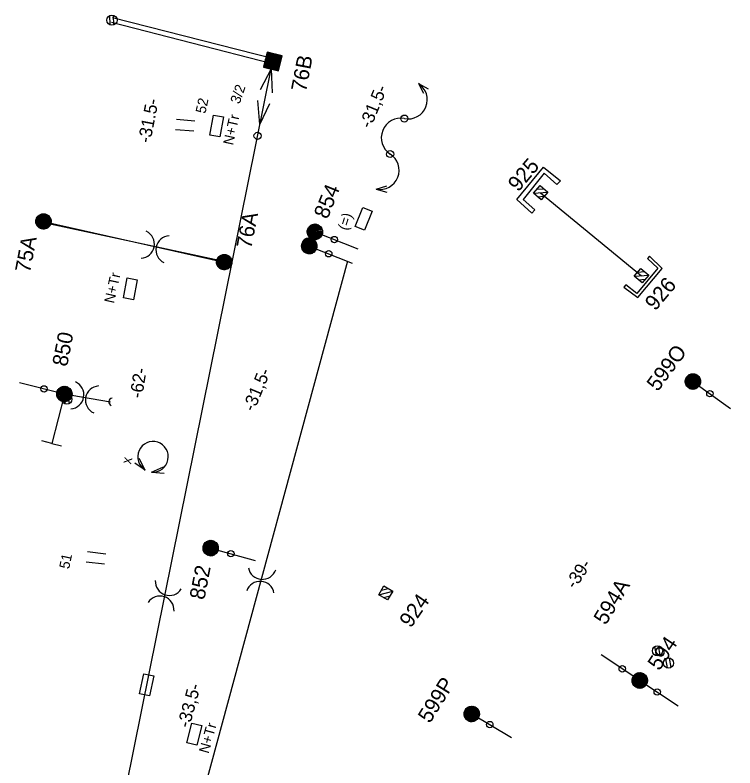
# Model space of a CAD drawing. Extents: x -595867 to -593796, y -1159595 to -1157495.
# Drawn here: x -594689.4 to -594618.9, y -1157851.2 to -1157777.4 of the extents above; entities that cross this region are included whole.
import ezdxf

# ---------------------------------------------------------------- set-up
doc = ezdxf.new("R2010")
doc.units = 0
for name, color, linetype in [('BVK_kanalizace_destova_nova', 7, 'Continuous'), ('BVK_kanalizace_jednotna_nova', 7, 'Continuous'), ('CD Telematika_novy', 7, 'Continuous'), ('Teplarny Horkovod', 7, 'Continuous')]:
    doc.layers.add(name, color=color, linetype=linetype)

# ---------------------------------------------------------------- blocks, each defined once
blk = doc.blocks.new('st_tecka')
blk.add_circle((0, 0), 0.00314)
blk = doc.blocks.new('st_1t')
for points in [[(-0.00711, 0.00221), (0.00057, 0.00744), (0.00185, 0.00722), (-0.00729, 0.00159)], [(-0.00689, 0.00294), (-0.00011, 0.00749), (0.00057, 0.00744), (-0.00711, 0.00221)], [(-0.00669, 0.00331), (-0.00149, 0.00733), (-0.00011, 0.00749), (-0.00689, 0.00294)], [(-0.00742, 0.00071), (0.00284, 0.0069), (0.00359, 0.00656), (-0.00747, -0.00023)], [(-0.00747, -0.00023), (0.00359, 0.00656), (0.00442, 0.00605), (-0.00743, -0.00101)], [(-0.00743, -0.00101), (0.00442, 0.00605), (0.00522, 0.0054), (-0.00722, -0.0019)], [(-0.00729, 0.00159), (0.00185, 0.00722), (0.00284, 0.0069), (-0.00742, 0.00071)], [(-0.00722, -0.0019), (0.00522, 0.0054), (0.00588, 0.00461), (-0.00688, -0.00302)], [(-0.00688, -0.00302), (0.00588, 0.00461), (0.00666, 0.00341), (-0.00639, -0.00386)], [(-0.00627, 0.00403), (-0.00222, 0.00714), (-0.00149, 0.00733), (-0.00669, 0.00331)], [(-0.00639, -0.00386), (0.00666, 0.00341), (0.00712, 0.00224), (-0.00567, -0.00488)], [(-0.00579, 0.00472), (-0.00315, 0.00675), (-0.00222, 0.00714), (-0.00627, 0.00403)], [(-0.00526, 0.00533), (-0.00413, 0.00624), (-0.00315, 0.00675), (-0.00579, 0.00472)], [(-0.00567, -0.00488), (0.00712, 0.00224), (0.00742, 0.00112), (-0.00488, -0.00564)], [(-0.00488, -0.00564), (0.00742, 0.00112), (0.00748, -0.00042), (-0.00405, -0.00629)], [(-0.00405, -0.00629), (0.00748, -0.00042), (0.00729, -0.00175), (-0.00317, -0.00679)], [(-0.00317, -0.00679), (0.00729, -0.00175), (0.00698, -0.00275), (-0.00206, -0.00718)], [(-0.00206, -0.00718), (0.00698, -0.00275), (0.00651, -0.0037), (-0.00114, -0.0074)], [(-0.00114, -0.0074), (0.00651, -0.0037), (0.00592, -0.00458), (-0.00048, -0.00747)], [(-0.00048, -0.00747), (0.00592, -0.00458), (0.00536, -0.00524), (0.00037, -0.00747)], [(0.00037, -0.00747), (0.00536, -0.00524), (0.00449, -0.00597), (0.00138, -0.00739)], [(0.00138, -0.00739), (0.00449, -0.00597), (0.00384, -0.00644), (0.0025, -0.00702)], [(0.0025, -0.00702), (0.00384, -0.00644), (0.00295, -0.00692), (0.00293, -0.00693)]]:
    blk.add_lwpolyline(points, close=True)
blk.add_circle((0, 0), 0.0075)
blk = doc.blocks.new('st1k_1t')
blk.add_line((0, 0), (0.04531, 0))
blk.add_blockref('st_1t', (0, 0))
at = {"rotation": 90}
blk.add_blockref('st_tecka', (0.02054, 0), dxfattribs=at)
blk = doc.blocks.new('st_2t')
for points in [[(-0.00748, 0.00968), (0.0002, 0.01491), (0.00148, 0.01469), (-0.00767, 0.00906)], [(-0.00727, 0.01041), (-0.00049, 0.01496), (0.0002, 0.01491), (-0.00748, 0.00968)], [(-0.00707, 0.01078), (-0.00187, 0.0148), (-0.00049, 0.01496), (-0.00727, 0.01041)], [(-0.00664, 0.0115), (-0.0026, 0.01461), (-0.00187, 0.0148), (-0.00707, 0.01078)], [(-0.00779, 0.00818), (0.00247, 0.01437), (0.00322, 0.01403), (-0.00784, 0.00724)], [(-0.00784, 0.00724), (0.00322, 0.01403), (0.00405, 0.01352), (-0.0078, 0.00646)], [(-0.0078, 0.00646), (0.00405, 0.01352), (0.00485, 0.01287), (-0.00759, 0.00557)], [(-0.00767, 0.00906), (0.00148, 0.01469), (0.00247, 0.01437), (-0.00779, 0.00818)], [(-0.00759, 0.00557), (0.00485, 0.01287), (0.0055, 0.01208), (-0.00725, 0.00445)], [(-0.00725, 0.00445), (0.0055, 0.01208), (0.00628, 0.01088), (-0.00676, 0.00361)], [(-0.00676, 0.00361), (0.00628, 0.01088), (0.00675, 0.00971), (-0.00604, 0.00259)], [(-0.00616, 0.01219), (-0.00352, 0.01422), (-0.0026, 0.01461), (-0.00664, 0.0115)], [(-0.00563, 0.0128), (-0.0045, 0.01371), (-0.00352, 0.01422), (-0.00616, 0.01219)], [(-0.00604, 0.00259), (0.00675, 0.00971), (0.00705, 0.00859), (-0.00525, 0.00183)], [(-0.00525, 0.00183), (0.00705, 0.00859), (0.00711, 0.00705), (-0.00442, 0.00118)], [(-0.00442, 0.00118), (0.00711, 0.00705), (0.00692, 0.00572), (-0.00354, 0.00068)], [(-0.00354, 0.00068), (0.00692, 0.00572), (0.00661, 0.00472), (-0.00243, 0.00029)], [(-0.00243, 0.00029), (0.00661, 0.00472), (0.00614, 0.00377), (-0.00151, 0.00007)], [(-0.00151, 0.00007), (0.00614, 0.00377), (0.00555, 0.00289), (-0.00086, 0)], [(-0.00086, 0), (0.00555, 0.00289), (0.00499, 0.00223), (0, 0)], [(0, 0), (0.00499, 0.00223), (0.00411, 0.0015), (0.001, 0.00008)], [(0.001, 0.00008), (0.00411, 0.0015), (0.00347, 0.00103), (0.00213, 0.00045)], [(0.00213, 0.00045), (0.00347, 0.00103), (0.00258, 0.00055), (0.00256, 0.00054)], [(-0.00779, -0.00682), (0.00247, -0.00063), (0.00322, -0.00097), (-0.00784, -0.00776)], [(-0.00784, -0.00776), (0.00322, -0.00097), (0.00405, -0.00148), (-0.0078, -0.00854)], [(-0.0078, -0.00854), (0.00405, -0.00148), (0.00485, -0.00213), (-0.00759, -0.00943)], [(-0.00767, -0.00594), (0.00148, -0.00031), (0.00247, -0.00063), (-0.00779, -0.00682)], [(-0.00748, -0.00532), (0.0002, -0.00009), (0.00148, -0.00031), (-0.00767, -0.00594)], [(-0.00759, -0.00943), (0.00485, -0.00213), (0.0055, -0.00292), (-0.00725, -0.01055)], [(-0.00727, -0.00459), (-0.00049, -0.00004), (0.0002, -0.00009), (-0.00748, -0.00532)], [(-0.00707, -0.00422), (-0.00187, -0.0002), (-0.00049, -0.00004), (-0.00727, -0.00459)], [(-0.00725, -0.01055), (0.0055, -0.00292), (0.00628, -0.00412), (-0.00676, -0.01139)], [(-0.00664, -0.0035), (-0.0026, -0.00039), (-0.00187, -0.0002), (-0.00707, -0.00422)], [(-0.00676, -0.01139), (0.00628, -0.00412), (0.00675, -0.00529), (-0.00604, -0.01241)], [(-0.00616, -0.00281), (-0.00352, -0.00078), (-0.0026, -0.00039), (-0.00664, -0.0035)], [(-0.00563, -0.0022), (-0.0045, -0.00129), (-0.00352, -0.00078), (-0.00616, -0.00281)], [(-0.00604, -0.01241), (0.00675, -0.00529), (0.00705, -0.00641), (-0.00525, -0.01317)], [(-0.00525, -0.01317), (0.00705, -0.00641), (0.00711, -0.00795), (-0.00442, -0.01382)], [(-0.00442, -0.01382), (0.00711, -0.00795), (0.00692, -0.00928), (-0.00354, -0.01432)], [(-0.00354, -0.01432), (0.00692, -0.00928), (0.00661, -0.01028), (-0.00243, -0.01471)], [(-0.00243, -0.01471), (0.00661, -0.01028), (0.00614, -0.01123), (-0.00151, -0.01493)], [(-0.00151, -0.01493), (0.00614, -0.01123), (0.00555, -0.01211), (-0.00086, -0.015)], [(-0.00086, -0.015), (0.00555, -0.01211), (0.00499, -0.01277), (0, -0.015)], [(0, -0.015), (0.00499, -0.01277), (0.00411, -0.0135), (0.001, -0.01492)], [(0.001, -0.01492), (0.00411, -0.0135), (0.00347, -0.01397), (0.00213, -0.01455)], [(0.00213, -0.01455), (0.00347, -0.01397), (0.00258, -0.01445), (0.00256, -0.01446)]]:
    blk.add_lwpolyline(points, close=True)
for centre in [(-0.00037, 0.00747), (-0.00037, -0.00753)]:
    blk.add_circle(centre, 0.0075)
blk = doc.blocks.new('st2k_2t')
for p, q in [((-0.00037, 0.00747), (0.04494, 0.00747)), ((-0.00037, -0.00753), (0.04494, -0.00753))]:
    blk.add_line(p, q)
blk.add_blockref('st_2t', (0, 0))
at = {"rotation": 90}
for p in [(0.02017, 0.00747), (0.02017, -0.00753)]:
    blk.add_blockref('st_tecka', p, dxfattribs=at)
blk = doc.blocks.new('pol_delic')
for p, q in [((-0.005, -0.00902), (-0.005, 0.00902)), ((0.005, -0.00902), (0.005, 0.00902))]:
    blk.add_line(p, q)
blk = doc.blocks.new('pol_izol')
for centre, start, end in [((-0.01484, 0), 284.40471, 75.59529), ((0.01484, 0), 104.40471, 255.59529)]:
    blk.add_arc(centre, 0.01384, start, end)
blk = doc.blocks.new('pol_sipka2')
for q in [(0.01228, 0.00302), (0.01182, -0.00341)]:
    blk.add_line((0, 0), q)
blk = doc.blocks.new('pol_sjsp')
for p, q in [((-0.01, 0.005), (0.01, 0.005)), ((-0.01, -0.005), (-0.01, 0.005)), ((0.01, 0.005), (0.01, -0.005)), ((0.01, -0.005), (-0.01, -0.005))]:
    blk.add_line(p, q)
blk = doc.blocks.new('st_bp')
for p, q in [((0.0075, 0.0075), (-0.0075, 0.0075)), ((-0.0075, 0.0075), (-0.0075, -0.0075)), ((-0.0075, -0.0075), (0.0075, 0.0075)), ((-0.0075, -0.00708), (0.00708, 0.0075)), ((-0.0075, -0.00665), (0.00665, 0.0075)), ((-0.0075, -0.00623), (0.00623, 0.0075)), ((-0.0075, -0.0058), (0.0058, 0.0075)), ((-0.0075, -0.00538), (0.00538, 0.0075)), ((-0.0075, -0.00495), (0.00495, 0.0075)), ((-0.0075, -0.00453), (0.00453, 0.0075)), ((-0.0075, -0.00411), (0.00411, 0.0075)), ((-0.0075, -0.00368), (0.00368, 0.0075)), ((-0.0075, -0.00326), (0.00326, 0.0075)), ((-0.0075, -0.00283), (0.00283, 0.0075)), ((-0.0075, -0.00241), (0.00241, 0.0075)), ((-0.0075, -0.00198), (0.00198, 0.0075)), ((-0.0075, -0.00156), (0.00156, 0.0075)), ((-0.0075, -0.00114), (0.00114, 0.0075)), ((-0.0075, -0.00071), (0.00071, 0.0075)), ((-0.0075, -0.00029), (0.00029, 0.0075)), ((-0.0075, 0.00014), (-0.00014, 0.0075)), ((-0.0075, 0.00056), (-0.00056, 0.0075)), ((-0.0075, 0.00099), (-0.00099, 0.0075)), ((-0.0075, 0.00141), (-0.00141, 0.0075)), ((-0.0075, 0.00183), (-0.00183, 0.0075)), ((-0.0075, 0.00226), (-0.00226, 0.0075)), ((-0.0075, 0.00268), (-0.00268, 0.0075)), ((-0.0075, 0.00311), (-0.00311, 0.0075)), ((-0.0075, 0.00353), (-0.00353, 0.0075)), ((-0.0075, 0.00396), (-0.00396, 0.0075)), ((-0.0075, 0.00438), (-0.00438, 0.0075)), ((-0.0075, 0.0048), (-0.0048, 0.0075)), ((-0.0075, 0.00523), (-0.00523, 0.0075)), ((-0.0075, 0.00565), (-0.00565, 0.0075)), ((-0.0075, 0.00608), (-0.00608, 0.0075)), ((-0.0075, 0.0065), (-0.0065, 0.0075)), ((-0.0075, 0.00692), (-0.00692, 0.0075)), ((-0.0075, 0.00735), (-0.00735, 0.0075)), ((0.0075, -0.0075), (0.0075, 0.0075)), ((-0.00708, -0.0075), (0.0075, 0.00708)), ((-0.00665, -0.0075), (0.0075, 0.00665)), ((-0.00623, -0.0075), (0.0075, 0.00623)), ((-0.0058, -0.0075), (0.0075, 0.0058)), ((-0.00538, -0.0075), (0.0075, 0.00538)), ((-0.00495, -0.0075), (0.0075, 0.00495)), ((-0.00453, -0.0075), (0.0075, 0.00453)), ((-0.00411, -0.0075), (0.0075, 0.00411)), ((-0.00368, -0.0075), (0.0075, 0.00368)), ((-0.00326, -0.0075), (0.0075, 0.00326)), ((-0.00283, -0.0075), (0.0075, 0.00283)), ((-0.00241, -0.0075), (0.0075, 0.00241)), ((-0.00198, -0.0075), (0.0075, 0.00198)), ((-0.00156, -0.0075), (0.0075, 0.00156)), ((-0.00114, -0.0075), (0.0075, 0.00114)), ((-0.00071, -0.0075), (0.0075, 0.00071)), ((-0.00029, -0.0075), (0.0075, 0.00029)), ((0.00014, -0.0075), (0.0075, -0.00014)), ((0.00056, -0.0075), (0.0075, -0.00056)), ((0.00099, -0.0075), (0.0075, -0.00099)), ((0.00141, -0.0075), (0.0075, -0.00141)), ((0.00183, -0.0075), (0.0075, -0.00183)), ((0.00226, -0.0075), (0.0075, -0.00226)), ((0.00268, -0.0075), (0.0075, -0.00268)), ((0.00311, -0.0075), (0.0075, -0.00311)), ((0.00353, -0.0075), (0.0075, -0.00353)), ((0.00396, -0.0075), (0.0075, -0.00396)), ((0.00438, -0.0075), (0.0075, -0.00438)), ((0.0048, -0.0075), (0.0075, -0.0048)), ((0.00523, -0.0075), (0.0075, -0.00523)), ((0.00565, -0.0075), (0.0075, -0.00565)), ((0.00608, -0.0075), (0.0075, -0.00608)), ((0.0065, -0.0075), (0.0075, -0.0065)), ((0.00692, -0.0075), (0.0075, -0.00692)), ((0.00735, -0.0075), (0.0075, -0.00735)), ((-0.0075, -0.0075), (0.0075, -0.0075))]:
    blk.add_line(p, q)
blk = doc.blocks.new('kotv_tecka')
blk.add_circle((0, 0), 0.00345)
blk = doc.blocks.new('kotv_polok')
for p, q in [((-0.05578, 0), (-0.03278, 0.00647)), ((-0.05578, 0), (-0.03363, -0.00562)), ((0, 0), (-0.02299, -0.00565))]:
    blk.add_line(p, q)
blk.add_lwpolyline([(0, 0), (-0.02214, 0.00639)])
blk.add_blockref('kotv_tecka', (-0.06698, 0))
blk = doc.blocks.new('st_pk')
for p, q in [((0, 0), (0, -0.05)), ((0, -0.05), (-0.01, -0.05)), ((0, -0.05), (0.01, -0.05))]:
    blk.add_line(p, q)
blk = doc.blocks.new('pol_propsestav')
for p, q in [((0, 0), (0.00098, -0.0108)), ((0, 0), (0.00678, -0.00864)), ((0.11129, -0.0001), (0.10434, -0.00843)), ((0.11129, -0.0001), (0.10996, -0.011))]:
    blk.add_line(p, q)
for centre, radius, start, end in [((0.05565, -0.00379), 0.01915, 11.42358, 168.57642), ((0.01844, 0.00339), 0.01875, 190.42183, 349.57817), ((0.09285, 0.00329), 0.01875, 190.42183, 349.57817)]:
    blk.add_arc(centre, radius, start, end)
for p in [(0.03688, 0), (0.07441, -0.0001)]:
    blk.add_blockref('kotv_tecka', p)
blk = doc.blocks.new('C661_3')
at = {"layer": 'Teplarny Horkovod'}
for p, q in [((-0.5, 0.033), (-0.033, 0.5)), ((-0.5, -0.497), (0.497, 0.5)), ((0.027, -0.5), (0.5, -0.027))]:
    blk.add_line(p, q, dxfattribs=at)
blk.add_lwpolyline([(-0.499, 0.5), (0.5, 0.499), (0.499, -0.5), (-0.5, -0.499)], close=True, dxfattribs=at)
blk.add_lwpolyline([(-0.499, 0.5), (0.5, 0.499), (0.499, -0.5), (-0.5, -0.499), (-0.499, 0.5)], dxfattribs=at)

msp = doc.modelspace()

# ---------------------------------------------------------------- linework, layer by layer
at = {"layer": 'BVK_kanalizace_destova_nova'}
msp.add_line((-594686.66, -1157797.65), (-594668.95, -1157801.64), dxfattribs=at)
at = {"layer": 'BVK_kanalizace_jednotna_nova'}
for p, q in [((-594680.127, -1157778.384), (-594680.164, -1157777.471)), ((-594679.752, -1157778.375), (-594679.79, -1157777.45)), ((-594663.53, -1157781.722), (-594664.85, -1157782.22)), ((-594664.01, -1157781.502), (-594664.635, -1157781.739)), ((-594663.748, -1157782.204), (-594664.366, -1157782.438)), ((-594686.741, -1157798.14), (-594686.96, -1157797.253)), ((-594686.376, -1157798.057), (-594686.597, -1157797.157)), ((-594660.287, -1157799.378), (-594660.501, -1157798.509)), ((-594659.917, -1157799.313), (-594660.144, -1157798.395)), ((-594660.808, -1157800.234), (-594661.022, -1157799.368)), ((-594660.438, -1157800.171), (-594660.664, -1157799.25)), ((-594669.031, -1157802.13), (-594669.25, -1157801.243)), ((-594668.666, -1157802.047), (-594668.887, -1157801.147)), ((-594622.746, -1157813.747), (-594622.967, -1157812.847)), ((-594623.111, -1157813.83), (-594623.33, -1157812.943)), ((-594684.493, -1157815.553), (-594684.653, -1157814.654)), ((-594684.123, -1157815.495), (-594684.285, -1157814.583)), ((-594670.277, -1157830.166), (-594670.643, -1157829.329)), ((-594669.93, -1157830.023), (-594670.302, -1157829.174)), ((-594626.602, -1157840.222), (-594626.762, -1157839.323)), ((-594626.232, -1157840.164), (-594626.394, -1157839.252)), ((-594625.532, -1157841.422), (-594625.692, -1157840.523)), ((-594625.162, -1157841.364), (-594625.324, -1157840.452)), ((-594644.697, -1157846.426), (-594645.063, -1157845.589)), ((-594644.35, -1157846.283), (-594644.722, -1157845.434))]:
    msp.add_line(p, q, dxfattribs=at)
for points in [[(-594664.254, -1157782.211), (-594680.012, -1157778.162)], [(-594664.129, -1157781.727), (-594679.887, -1157777.677)], [(-594663.94, -1157782.63), (-594664.851, -1157782.219), (-594664.441, -1157781.308), (-594663.529, -1157781.719), (-594663.94, -1157782.63)], [(-594669.445, -1157801.479), (-594686.021, -1157797.923)]]:
    msp.add_lwpolyline(points, dxfattribs=at)
msp.add_lwpolyline([(-594663.94, -1157782.63), (-594664.851, -1157782.219), (-594664.441, -1157781.308), (-594663.529, -1157781.719)], close=True, dxfattribs=at)
for centre in [(-594679.95, -1157777.92), (-594679.95, -1157777.92), (-594686.66, -1157797.65), (-594686.66, -1157797.65), (-594660.181, -1157798.892), (-594660.181, -1157798.892), (-594660.699, -1157799.748), (-594660.699, -1157799.748), (-594668.95, -1157801.64), (-594668.95, -1157801.64), (-594623.03, -1157813.34), (-594623.03, -1157813.34), (-594684.38, -1157815.07), (-594684.38, -1157815.07), (-594670.28, -1157829.67), (-594670.28, -1157829.67), (-594626.489, -1157839.739), (-594626.489, -1157839.739), (-594625.419, -1157840.939), (-594625.419, -1157840.939), (-594644.7, -1157845.93), (-594644.7, -1157845.93)]:
    msp.add_circle(centre, 0.5, dxfattribs=at)
at = {"layer": 'CD Telematika_novy'}
for p, q in [((-594679.628, -1157858.372), (-594664.363, -1157782.697)), ((-594656.862, -1157801.534), (-594673.638, -1157863.365)), ((-594683.87, -1157814.681), (-594680.101, -1157815.35))]:
    msp.add_line(p, q, dxfattribs=at)
for centre, radius, start, end in [((-594679.882, -1157815.338), 0.374, 99.08175, 249.05006), ((-594675.93, -1157820.721), 1.5, 264.66669, 239.81944)]:
    msp.add_arc(centre, radius, start, end, dxfattribs=at)
at = {"layer": 'Teplarny Horkovod'}
msp.add_line((-594637.957, -1157794.84), (-594628.063, -1157802.972), dxfattribs=at)
for points in [[(-594638.824, -1157796.847), (-594640.28, -1157795.514), (-594637.667, -1157792.323), (-594636.003, -1157793.664), (-594636.347, -1157794.027), (-594637.595, -1157792.913), (-594639.669, -1157795.509), (-594638.527, -1157796.504)], [(-594629.802, -1157804.082), (-594628.432, -1157805.119), (-594626.053, -1157802.269), (-594627.282, -1157801.064), (-594627.475, -1157801.286), (-594626.474, -1157802.221), (-594628.522, -1157804.703), (-594629.608, -1157803.861)]]:
    msp.add_lwpolyline(points, close=True, dxfattribs=at)

# ---------------------------------------------------------------- block references
at = {"layer": 'BVK_kanalizace_destova_nova'}
for name, p, xscale, yscale, rotation in [('st_bp', (-594664.19, -1157781.97), 100.00000000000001, 99.99999999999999, 165.92225640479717), ('kotv_polok', (-594664.362, -1157782.695), 100.00000000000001, 99.99999999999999, 78.57142426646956), ('pol_propsestav', (-594654.058, -1157794.472), 100, 99.99999999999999, 68.28133002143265), ('pol_sjsp', (-594655.289, -1157797.398), 99.99999999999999, 100.00000000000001, 68.31915110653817), ('st_1t', (-594686.66, -1157797.65), 100.00000000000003, 99.99999999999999, 79.51685128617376), ('st2k_2t', (-594660.309, -1157799.378), 99.99999999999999, 100, -21.61315544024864), ('pol_izol', (-594675.721, -1157800.154), 99.99999999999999, 100, -11.00881475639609), ('st_1t', (-594668.95, -1157801.64), 100.00000000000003, 99.99999999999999, 79.51685128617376), ('st1k_1t', (-594684.614, -1157814.57), 100.00000000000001, 100, 165.8571297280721), ('st1k_1t', (-594623.03, -1157813.34), 100, 100, -35.60665685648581), ('st_pk', (-594684.614, -1157814.57), 100, 99.99999999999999, -14.374467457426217), ('st1k_1t', (-594670.28, -1157829.67), 100, 100, -15.40879640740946), ('st1k_1t', (-594628.236, -1157842.644), 100, 100, 146.43280964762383), ('st1k_1t', (-594628.236, -1157842.644), 100, 100, -33.51023950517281), ('st1k_1t', (-594644.7, -1157845.93), 100, 100.00000000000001, -30.55428836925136)]:
    msp.add_blockref(name, p, dxfattribs=dict(at, xscale=xscale, yscale=yscale, rotation=rotation))
at = {"layer": 'CD Telematika_novy'}
for name, p, xscale, yscale, rotation in [('pol_delic', (-594672.77, -1157788.238), 100.00000000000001, 99.99999999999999, 84.93573336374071), ('pol_sjsp', (-594669.695, -1157788.292), 100, 100, 79.84609048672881), ('pol_sjsp', (-594678.141, -1157804.251), 99.99999999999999, 100.00000000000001, 79.43012523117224), ('pol_izol', (-594682.627, -1157814.904), 100, 100.00000000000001, -9.955608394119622), ('pol_sipka2', (-594676.684, -1157822.018), 100, -100, 131.78622154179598), ('pol_sipka2', (-594676.069, -1157822.215), 100.00000000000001, 100, 10.552958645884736), ('pol_delic', (-594681.514, -1157830.645), 100.00000000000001, 99.99999999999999, 83.40368125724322), ('pol_izol', (-594665.329, -1157832.837), 99.99999999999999, 100, 85.75215275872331), ('pol_izol', (-594674.788, -1157834.344), 100.00000000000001, 99.99999999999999, 71.74538383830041), ('pol_sjsp', (-594676.551, -1157843.065), 100, 100, 78.34969746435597), ('pol_sjsp', (-594671.884, -1157847.916), 100.00000000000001, 99.99999999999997, 76.28857358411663)]:
    msp.add_blockref(name, p, dxfattribs=dict(at, xscale=xscale, yscale=yscale, rotation=rotation))
at = {"layer": 'Teplarny Horkovod'}
for p, xscale, yscale, rotation in [((-594637.957, -1157794.84), 0.9999987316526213, 0.9999987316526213, -40.86817155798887), ((-594628.063, -1157802.972), 1.0000006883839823, 1.0000006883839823, -40.38265978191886), ((-594653.125, -1157834.07), 1.0000015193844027, 1.0000015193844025, -30.379022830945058)]:
    msp.add_blockref('C661_3', p, dxfattribs=dict(at, xscale=xscale, yscale=yscale, rotation=rotation))

# ---------------------------------------------------------------- texts
at = {"layer": 'BVK_kanalizace_destova_nova'}
for s, height, rotation, p in [('76B', 1.5, 79.02055, (-594660.948, -1157785.015)), ('3/2', 1, 70.78041, (-594667.453, -1157786.198)), ('-31,5-', 1.25, 67.43502, (-594654.614, -1157788.613)), ('-31.5-', 1.25, 78.80914, (-594676.204, -1157790.027)), ('854', 1.5, 67.88808, (-594658.839, -1157797.5)), ('76A', 1.5, 79.02055, (-594666.308, -1157800.392)), ('(=)', 1, 72.16266, (-594656.892, -1157798.594)), ('75A', 1.5, 79.02055, (-594687.993, -1157802.752)), ('850', 1.5, 79.02055, (-594684.348, -1157811.941)), ('599O', 1.5, 53.58283, (-594626.469, -1157814.398)), ('-62-', 1.25, 80.87768, (-594677.004, -1157815.046)), ('-31,5-', 1.25, 67.43502, (-594666.039, -1157816.371)), ('-39-', 1.25, 56.49181, (-594634.573, -1157833.76)), ('852', 1.5, 79.02055, (-594670.902, -1157834.809)), ('594', 1.5, 56.09715, (-594626.33, -1157841.772)), ('599P', 1.5, 58.00758, (-594648.803, -1157846.926)), ('-33,5-', 1.25, 74.90993, (-594672.369, -1157847.36))]:
    msp.add_text(s, height=height, rotation=rotation, dxfattribs=at).set_placement(p)
at = {"layer": 'BVK_kanalizace_jednotna_nova'}
msp.add_text('594A', height=1.5, rotation=58.68454, dxfattribs=at).set_placement((-594631.576, -1157837.295))
at = {"layer": 'CD Telematika_novy'}
for s, rotation, p in [('52', 77.795, (-594670.797, -1157787.13)), ('N+Tr', 77.6158, (-594668.094, -1157790.23)), ('N+Tr', 77.6158, (-594679.75, -1157805.736)), ('x', 77.795, (-594678.086, -1157821.506)), ('51', 77.795, (-594684.161, -1157831.781)), ('N+Tr', 74.34606, (-594670.49, -1157849.867))]:
    msp.add_text(s, height=1, rotation=rotation, dxfattribs=at).set_placement(p)
at = {"layer": 'Teplarny Horkovod'}
for s, rotation, p in [('925', 49.85362, (-594640.143, -1157794.822)), ('926', 49.85362, (-594626.722, -1157806.489)), ('924', 55.15079, (-594650.671, -1157837.577))]:
    msp.add_text(s, height=1.5, rotation=rotation, dxfattribs=at).set_placement(p)

doc.saveas('drawing.dxf')
